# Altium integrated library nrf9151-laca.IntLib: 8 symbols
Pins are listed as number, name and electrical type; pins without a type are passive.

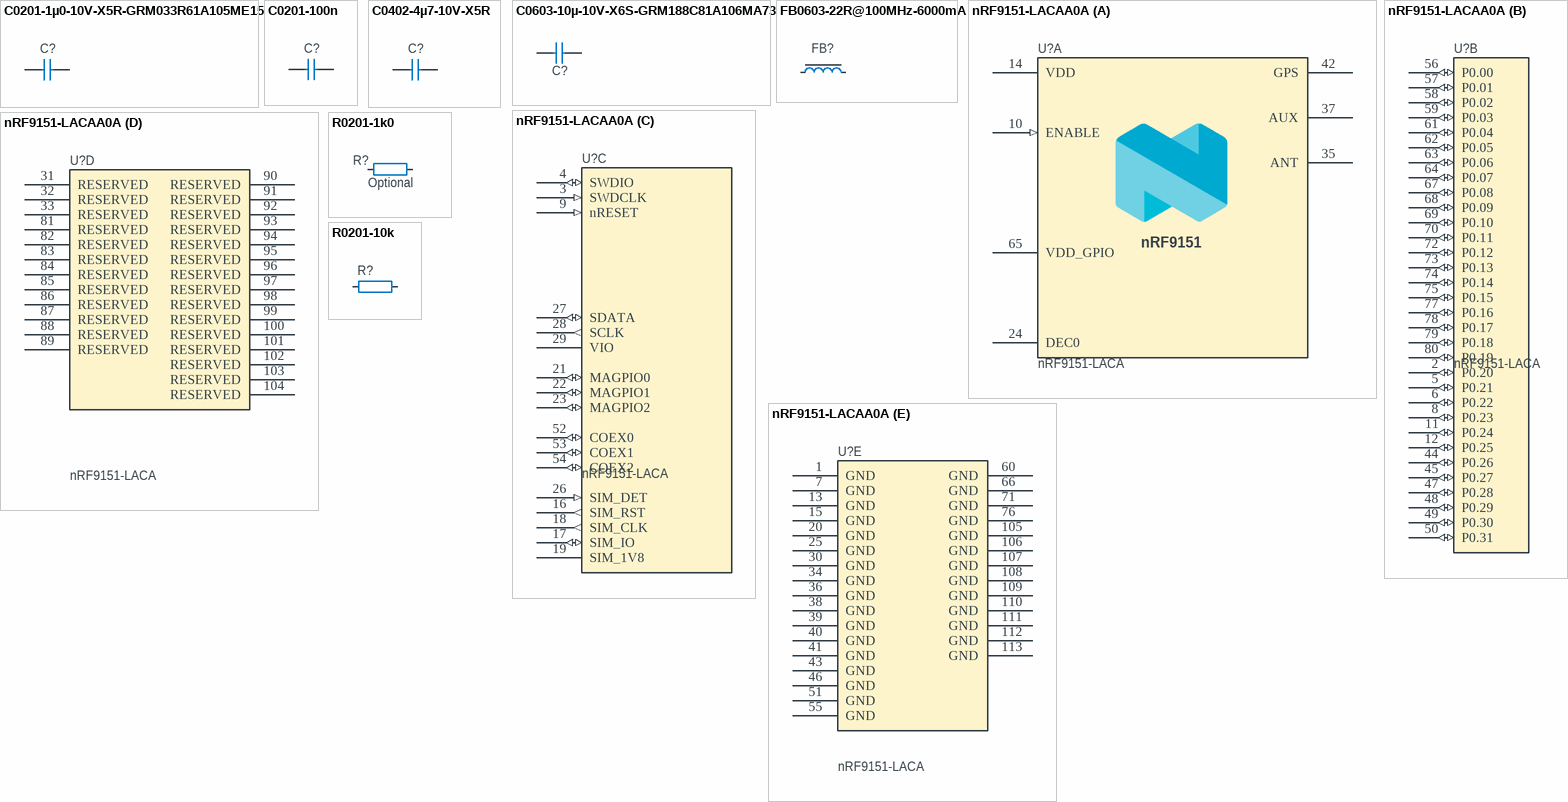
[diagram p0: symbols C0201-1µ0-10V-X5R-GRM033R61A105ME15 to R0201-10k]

## C0201-1µ0-10V-X5R-GRM033R61A105ME15
designator C?, comment 1.0µF  (value not drawn)
Capacitor, X5R, ±20%, 10V; Part Number: C0201-1µ0-10V-X5R-GRM033R61A105ME15; Manufacturer: Murata; Manufacturer Part Number: GRM033R61A105ME15; Part number NEMS: 100200545; Artikkelnr Noca: N.A.; Pad Count: 2; Component Status: Active
footprint CAPC0603X03L_C
pins: 1, 2

## C0201-100n
designator C?, comment 100nF  (value not drawn)
Capacitor, X5R, ±10%; Part Number: C0201-100n; Pad Count: 2
footprint CAPC0603X03L_C
pins: 1, 2

## C0402-4µ7-10V-X5R
designator C?, comment 4.7µF  (value not drawn)
Capacitor, X5R, 10V; Part Number: C0402-4µ7-10V-X5R; Manufacturer: Murata; Manufacturer Part Number: GRM155R61A475MEAAD; Part number NEMS: 100200415; Artikkelnr Noca: N.A.; Pad Count: 2; Component Status: Active
footprint CAPC1005X04L
pins: 1, 2

## C0603-10µ-10V-X6S-GRM188C81A106MA73
designator C?, comment 10µF  (value not drawn)
Capacitor, Ceramic, 10µF 10V X6S 0603,±20%; Part Number: C0603-10µ-10V-X6S-GRM188C81A106MA73; Manufacturer: Murata; Manufacturer Part Number: GRM188C81A106MA73; Part number NEMS: 100200520; Component Status: Active; Pad Count: 2; Artikkelnr Noca: N.A.
footprint CAPC1608X06L
pins: 1, 2

## FB0603-22R@100MHz-6000mA
designator FB?, comment 22R@100M/6A  (value not drawn)
Ferrite Bead, 22 Ohm @ 100MHz, 6000mA, 8 mOhm Max; Part Number: FB0603-22R@100MHz-6000mA; Manufacturer: Murata; Manufacturer Part Number: BLM18SD220SN1D; Component Status: Active; Pad Count: 2; Note: Chip EMIFIL Inductor Type Chip Ferrite Bead; Artikkelnr Noca: N.A.
footprint INDC1608X06L
pins: 1, 2

## nRF9151-LACAA0A
designator U?, comment nRF9151-LACA
Low power System-in-Package with integrated LTE-M/NB-IoT modem and GPS; Part Number: nRF9151-LACAA0A; Manufacturer: Nordic Semiconductor; Part number NEMS: 102000328; Pad Count: 113; Component Status: Active; Note: N.A.
footprint LGA50P1210X1110X130-113N
part A pins: 10 ENABLE (in), 14 VDD (power), 24 DEC0, 35 ANT, 37 AUX, 42 GPS, 65 VDD_GPIO (power)
part B pins: 2 P0.20 (io), 5 P0.21 (io), 6 P0.22 (io), 8 P0.23 (io), 11 P0.24 (io), 12 P0.25 (io), 44 P0.26 (io), 45 P0.27 (io), 47 P0.28 (io), 48 P0.29 (io), 49 P0.30 (io), 50 P0.31 (io), 56 P0.00 (io), 57 P0.01 (io), 58 P0.02 (io), 59 P0.03 (io), 61 P0.04 (io), 62 P0.05 (io), 63 P0.06 (io), 64 P0.07 (io), 67 P0.08 (io), 68 P0.09 (io), 69 P0.10 (io), 70 P0.11 (io), 72 P0.12 (io), 73 P0.13 (io), 74 P0.14 (io), 75 P0.15 (io), 77 P0.16 (io), 78 P0.17 (io), 79 P0.18 (io), 80 P0.19 (io)
part C pins: 3 SWDCLK (in), 4 SWDIO (io), 9 nRESET (in), 16 SIM_RST (out), 17 SIM_IO (io), 18 SIM_CLK (out), 19 SIM_1V8 (power), 21 MAGPIO0 (io), 22 MAGPIO1 (io), 23 MAGPIO2 (io), 26 SIM_DET (in), 27 SDATA (io), 28 SCLK (out), 29 VIO, 52 COEX0 (io), 53 COEX1 (io), 54 COEX2 (io)
part D pins: 31 RESERVED, 32 RESERVED, 33 RESERVED, 81 RESERVED, 82 RESERVED, 83 RESERVED, 84 RESERVED, 85 RESERVED, 86 RESERVED, 87 RESERVED, 88 RESERVED, 89 RESERVED, 90 RESERVED, 91 RESERVED, 92 RESERVED, 93 RESERVED, 94 RESERVED, 95 RESERVED, 96 RESERVED, 97 RESERVED, 98 RESERVED, 99 RESERVED, 100 RESERVED, 101 RESERVED, 102 RESERVED, 103 RESERVED, 104 RESERVED
part E pins: 1 GND, 7 GND, 13 GND, 15 GND, 20 GND, 25 GND, 30 GND, 34 GND, 36 GND, 38 GND, 39 GND, 40 GND, 41 GND, 43 GND, 46 GND, 51 GND, 55 GND, 60 GND, 66 GND, 71 GND, 76 GND, 105 GND, 106 GND, 107 GND, 108 GND, 109 GND, 110 GND, 111 GND, 112 GND, 113 GND

## R0201-1k0
designator R?, comment Assembly: Optional  (hidden comment: 1k)
Resistor, ±1%, 0.05W; Part Number: R0201-1k0; Pad Count: 2
footprint RESC0603X03L_C
pins: 1, 2

## R0201-10k
designator R?, comment 10k  (value not drawn)
Resistor, ±1%, 0.05W; Part Number: R0201-10k; Manufacturer: N.A.; Part number IPS: 00000001255; Part number Norautron: 26107101; Part number NEMS: 100100065; Note: Chip Res 1%; Pad Count: 2; Component Status: Active
footprint RESC0603X03L_C
pins: 1, 2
